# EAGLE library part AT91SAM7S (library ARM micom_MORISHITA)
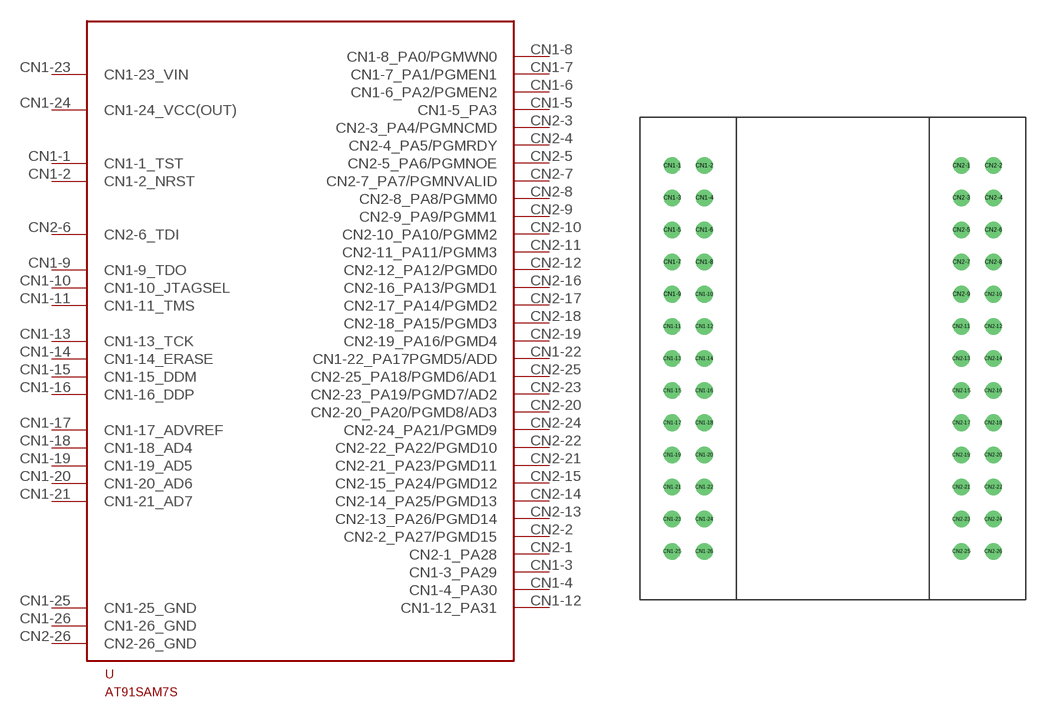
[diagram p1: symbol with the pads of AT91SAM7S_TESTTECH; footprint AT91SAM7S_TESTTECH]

Designator prefix U

## AT91SAM7SBEST_TECH  [AT91SAM7S_TESTTECH]
CN1-1  CN1-1_TST
CN1-2  CN1-2_NRST
CN1-3  CN1-3_PA29
CN1-4  CN1-4_PA30
CN1-5  CN1-5_PA3
CN1-6  CN1-6_PA2/PGMEN2
CN1-7  CN1-7_PA1/PGMEN1
CN1-8  CN1-8_PA0/PGMWN0
CN1-9  CN1-9_TDO
CN1-10  CN1-10_JTAGSEL
CN1-11  CN1-11_TMS
CN1-12  CN1-12_PA31
CN1-13  CN1-13_TCK
CN1-14  CN1-14_ERASE
CN1-15  CN1-15_DDM
CN1-16  CN1-16_DDP
CN1-17  CN1-17_ADVREF
CN1-18  CN1-18_AD4
CN1-19  CN1-19_AD5
CN1-20  CN1-20_AD6
CN1-21  CN1-21_AD7
CN1-22  CN1-22_PA17PGMD5/ADD
CN1-23  CN1-23_VIN
CN1-24  CN1-24_VCC(OUT)  pwr
CN1-25  CN1-25_GND  pwr
CN1-26  CN1-26_GND  pwr
CN2-1  CN2-1_PA28
CN2-2  CN2-2_PA27/PGMD15
CN2-3  CN2-3_PA4/PGMNCMD
CN2-4  CN2-4_PA5/PGMRDY
CN2-5  CN2-5_PA6/PGMNOE
CN2-6  CN2-6_TDI
CN2-7  CN2-7_PA7/PGMNVALID
CN2-8  CN2-8_PA8/PGMM0
CN2-9  CN2-9_PA9/PGMM1
CN2-10  CN2-10_PA10/PGMM2
CN2-11  CN2-11_PA11/PGMM3
CN2-12  CN2-12_PA12/PGMD0
CN2-13  CN2-13_PA26/PGMD14
CN2-14  CN2-14_PA25/PGMD13
CN2-15  CN2-15_PA24/PGMD12
CN2-16  CN2-16_PA13/PGMD1
CN2-17  CN2-17_PA14/PGMD2
CN2-18  CN2-18_PA15/PGMD3
CN2-19  CN2-19_PA16/PGMD4
CN2-20  CN2-20_PA20/PGMD8/AD3
CN2-21  CN2-21_PA23/PGMD11
CN2-22  CN2-22_PA22/PGMD10
CN2-23  CN2-23_PA19/PGMD7/AD2
CN2-24  CN2-24_PA21/PGMD9
CN2-25  CN2-25_PA18/PGMD6/AD1
CN2-26  CN2-26_GND  pwr

## Footprint AT91SAM7S_TESTTECH (pad centres in mm)
AT91SAM7S Best Technology micom board ARM7 micom series. producted by ATMEL.Co
drill 0.8 round: CN1-1 -12.7,15.24; CN1-2 -10.16,15.24; CN1-3 -12.7,12.7; CN1-4 -10.16,12.7; CN1-5 -12.7,10.16; CN1-6 -10.16,10.16; CN1-7 -12.7,7.62; CN1-8 -10.16,7.62; CN1-9 -12.7,5.08; CN1-10 -10.16,5.08; CN1-11 -12.7,2.54; CN1-12 -10.16,2.54; CN1-13 -12.7,0; CN1-14 -10.16,0; CN1-15 -12.7,-2.54; CN1-16 -10.16,-2.54; CN1-17 -12.7,-5.08; CN1-18 -10.16,-5.08; CN1-19 -12.7,-7.62; CN1-20 -10.16,-7.62; CN1-21 -12.7,-10.16; CN1-22 -10.16,-10.16; CN1-23 -12.7,-12.7; CN1-24 -10.16,-12.7; CN1-25 -12.7,-15.24; CN1-26 -10.16,-15.24; CN2-1 10.16,15.24; CN2-2 12.7,15.24; CN2-3 10.16,12.7; CN2-4 12.7,12.7; CN2-5 10.16,10.16; CN2-6 12.7,10.16; CN2-7 10.16,7.62; CN2-8 12.7,7.62; CN2-9 10.16,5.08; CN2-10 12.7,5.08; CN2-11 10.16,2.54; CN2-12 12.7,2.54; CN2-13 10.16,0; CN2-14 12.7,0; CN2-15 10.16,-2.54; CN2-16 12.7,-2.54; CN2-17 10.16,-5.08; CN2-18 12.7,-5.08; CN2-19 10.16,-7.62; CN2-20 12.7,-7.62; CN2-21 10.16,-10.16; CN2-22 12.7,-10.16; CN2-23 10.16,-12.7; CN2-24 12.7,-12.7; CN2-25 10.16,-15.24; CN2-26 12.7,-15.24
